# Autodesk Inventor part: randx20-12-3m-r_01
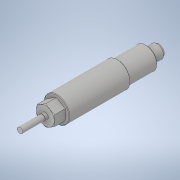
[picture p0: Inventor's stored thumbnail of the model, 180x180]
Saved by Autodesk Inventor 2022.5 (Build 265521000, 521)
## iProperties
Created: 2021-02
Part Number: randx20-12-3m-r_01
Material: 一般
Document SubType Name: Modeling
Designer: ImaoCorp
Density: 1 g/cm^3
Appearance: 既定
Author: ImaoCorp
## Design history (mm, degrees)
feature "randx20-12-3m-r_01"
node "ソリッド1"
